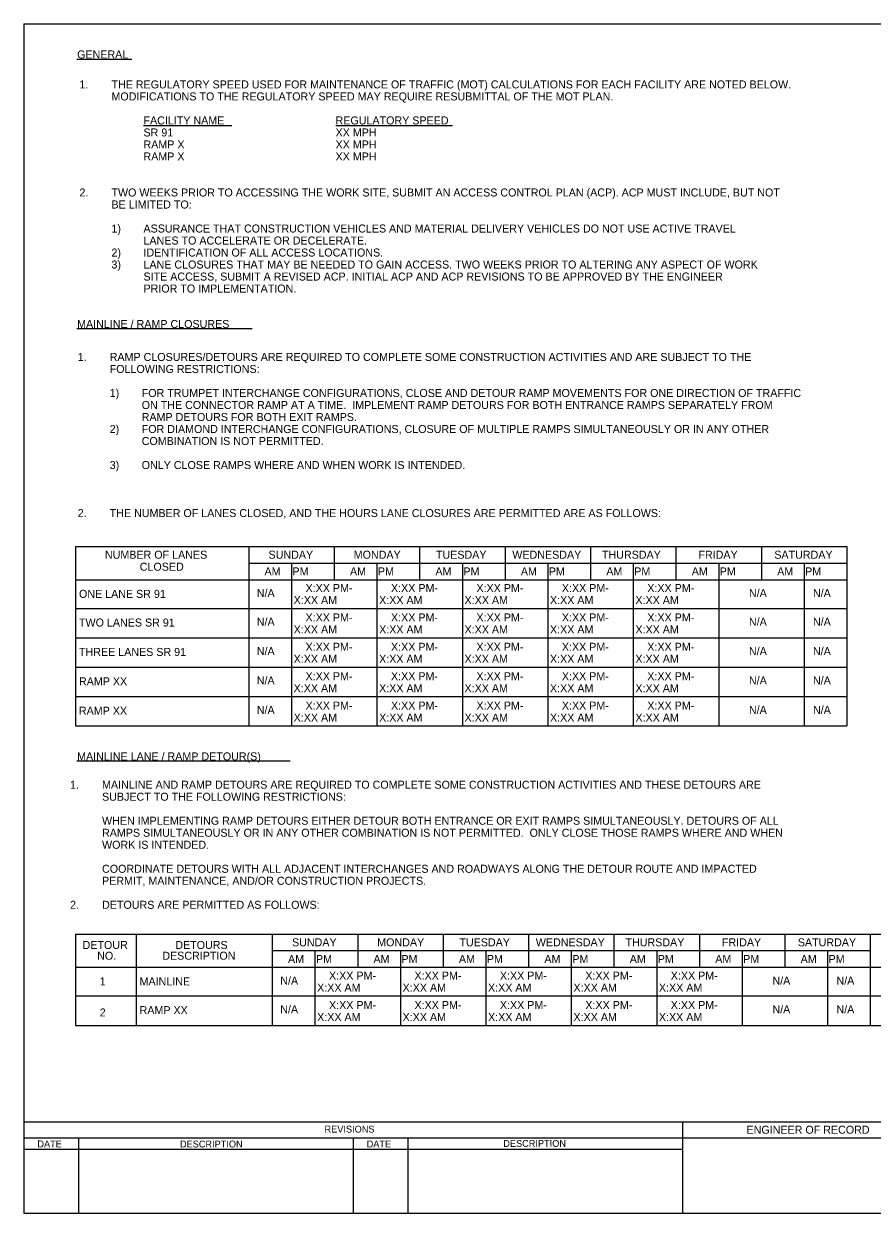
# Model space of a CAD drawing. Extents: x -0.71 to 1.34, y 0 to 0.87.
# Drawn here: x 0.046 to 0.664, y 0.004 to 0.871 of the extents above; entities that cross this region are included whole.
import ezdxf

# ---------------------------------------------------------------- set-up
doc = ezdxf.new("R2010")
doc.units = 0
for name, color, linetype in [('Default', 7, 'Continuous'), ('SheetBorder_dp', 7, 'Continuous'), ('SheetLines_dp', 7, 'Continuous'), ('TextLabel', 7, 'Continuous'), ('TextMisc', 7, 'Continuous')]:
    doc.layers.add(name, color=color, linetype=linetype)

msp = doc.modelspace()

# ---------------------------------------------------------------- linework, layer by layer
at = {"layer": 'Default'}
for p, q in [((0.08359, 0.49003), (0.6457, 0.49003)), ((0.08359, 0.49003), (0.08359, 0.35923)), ((0.2098, 0.49003), (0.2098, 0.35923)), ((0.27207, 0.49003), (0.27207, 0.46576)), ((0.33434, 0.49003), (0.33434, 0.46576)), ((0.39661, 0.49003), (0.39661, 0.46576)), ((0.45888, 0.49003), (0.45888, 0.46576)), ((0.52116, 0.49003), (0.52116, 0.46576)), ((0.58343, 0.49003), (0.58343, 0.46576)), ((0.6457, 0.49003), (0.6457, 0.35923)), ((0.2098, 0.4779), (0.6457, 0.4779)), ((0.24094, 0.4779), (0.24094, 0.35923)), ((0.30321, 0.4779), (0.30321, 0.35923)), ((0.36548, 0.4779), (0.36548, 0.35923)), ((0.42775, 0.4779), (0.42775, 0.35923)), ((0.49002, 0.4779), (0.49002, 0.35923)), ((0.55229, 0.4779), (0.55229, 0.35923)), ((0.61456, 0.4779), (0.61456, 0.35923)), ((0.08359, 0.46576), (0.6457, 0.46576)), ((0.08359, 0.44488), (0.6457, 0.44488)), ((0.08359, 0.42347), (0.6457, 0.42347)), ((0.08359, 0.40205), (0.6457, 0.40205)), ((0.08359, 0.38064), (0.6457, 0.38064)), ((0.08359, 0.35923), (0.6457, 0.35923)), ((0.08359, 0.20761), (0.74834, 0.20761)), ((0.08359, 0.20761), (0.08359, 0.14105)), ((0.12776, 0.20761), (0.12776, 0.14105)), ((0.22691, 0.20761), (0.22691, 0.14105)), ((0.28919, 0.20761), (0.28919, 0.18334)), ((0.35146, 0.20761), (0.35146, 0.18334)), ((0.41373, 0.20761), (0.41373, 0.18334)), ((0.476, 0.20761), (0.476, 0.18334)), ((0.53827, 0.20761), (0.53827, 0.18334)), ((0.60054, 0.20761), (0.60054, 0.18334)), ((0.66281, 0.20761), (0.66281, 0.14105)), ((0.22691, 0.19548), (0.66281, 0.19548)), ((0.25805, 0.19548), (0.25805, 0.14105)), ((0.32032, 0.19548), (0.32032, 0.14105)), ((0.38259, 0.19548), (0.38259, 0.14105)), ((0.44486, 0.19548), (0.44486, 0.14105)), ((0.50713, 0.19548), (0.50713, 0.14105)), ((0.56941, 0.19548), (0.56941, 0.14105)), ((0.63168, 0.19548), (0.63168, 0.14105)), ((0.08359, 0.18334), (0.74834, 0.18334)), ((0.08359, 0.16246), (0.74834, 0.16246)), ((0.08359, 0.14105), (0.74834, 0.14105))]:
    msp.add_line(p, q, dxfattribs=at)
at = {"layer": 'SheetBorder_dp'}
for p, q in [((0.04583, 0.87083), (0.04583, 0.00417)), ((0.04583, 0.87083), (1.32916, 0.87083)), ((0.04583, 0.07083), (1.32916, 0.07083)), ((0.04583, 0.00417), (1.32916, 0.00417))]:
    msp.add_line(p, q, dxfattribs=at)
at = {"layer": 'SheetLines_dp'}
for p, q in [((0.52583, 0.07083), (0.52583, 0.00417)), ((0.04583, 0.05917), (0.52583, 0.05917)), ((0.08583, 0.05917), (0.08583, 0.00417)), ((0.28583, 0.05917), (0.28583, 0.00417)), ((0.32583, 0.05917), (0.32583, 0.00417)), ((0.52621, 0.05917), (0.72084, 0.05917)), ((0.04583, 0.05083), (0.52583, 0.05083))]:
    msp.add_line(p, q, dxfattribs=at)
at = {"layer": 'TextLabel'}
for p, q in [((0.08444, 0.84513), (0.1246, 0.84513)), ((0.13314, 0.79678), (0.19739, 0.79678)), ((0.27326, 0.79678), (0.35823, 0.79678)), ((0.08444, 0.64875), (0.21227, 0.64875)), ((0.08444, 0.33368), (0.2401, 0.33368))]:
    msp.add_line(p, q, dxfattribs=at)

# ---------------------------------------------------------------- texts
at = {"layer": 'Default'}
for s, height, p in [('NUMBER OF LANES', 0.0058333, (0.10498, 0.48105)), ('SUNDAY', 0.005833, (0.22422, 0.48105)), ('MONDAY', 0.005833, (0.2863, 0.48105)), ('TUESDAY', 0.005833, (0.34622, 0.48105)), ('WEDNESDAY', 0.005833, (0.40188, 0.48105)), ('THURSDAY', 0.005833, (0.46724, 0.48105)), ('FRIDAY', 0.005833, (0.53753, 0.48105)), ('SATURDAY', 0.005833, (0.59284, 0.48105)), ('CLOSED', 0.005833, (0.13035, 0.4723)), ('AM    PM', 0.005833, (0.22131, 0.46891)), ('AM    PM', 0.005833, (0.28358, 0.46891)), ('AM    PM', 0.005833, (0.34585, 0.46891)), ('AM    PM', 0.005833, (0.40812, 0.46891)), ('AM    PM', 0.005833, (0.47039, 0.46891)), ('AM    PM', 0.005833, (0.53267, 0.46891)), ('AM    PM', 0.005833, (0.59494, 0.46891)), (' X:XX PM-', 0.005833, (0.24903, 0.45678)), (' X:XX PM-', 0.005833, (0.3113, 0.45678)), (' X:XX PM-', 0.005833, (0.37357, 0.45678)), (' X:XX PM-', 0.005833, (0.43584, 0.45678)), (' X:XX PM-', 0.005833, (0.49811, 0.45678)), ('ONE LANE SR 91', 0.0058333, (0.08607, 0.45252)), ('N/A', 0.005833, (0.21566, 0.45314)), ('      X:XX AM', 0.0058333, (0.22953, 0.44803)), ('      X:XX AM', 0.0058333, (0.2918, 0.44803)), ('      X:XX AM', 0.0058333, (0.35407, 0.44803)), ('      X:XX AM', 0.0058333, (0.41634, 0.44803)), ('      X:XX AM', 0.0058333, (0.47861, 0.44803)), ('N/A', 0.005833, (0.57437, 0.45314)), ('N/A', 0.005833, (0.62103, 0.45314)), ('TWO LANES SR 91', 0.0058333, (0.08607, 0.43164)), ('N/A', 0.005833, (0.21566, 0.43226)), (' X:XX PM-', 0.005833, (0.24903, 0.43537)), (' X:XX PM-', 0.005833, (0.3113, 0.43537)), (' X:XX PM-', 0.005833, (0.37357, 0.43537)), (' X:XX PM-', 0.005833, (0.43584, 0.43537)), (' X:XX PM-', 0.005833, (0.49811, 0.43537)), ('N/A', 0.005833, (0.57437, 0.43226)), ('N/A', 0.005833, (0.62103, 0.43226)), ('      X:XX AM', 0.0058333, (0.22953, 0.42662)), ('      X:XX AM', 0.0058333, (0.2918, 0.42662)), ('      X:XX AM', 0.0058333, (0.35407, 0.42662)), ('      X:XX AM', 0.0058333, (0.41634, 0.42662)), ('      X:XX AM', 0.0058333, (0.47861, 0.42662)), ('THREE LANES SR 91', 0.0058333, (0.08607, 0.41022)), ('N/A', 0.005833, (0.21566, 0.41085)), (' X:XX PM-', 0.005833, (0.24903, 0.41395)), (' X:XX PM-', 0.005833, (0.3113, 0.41395)), (' X:XX PM-', 0.005833, (0.37357, 0.41395)), (' X:XX PM-', 0.005833, (0.43584, 0.41395)), (' X:XX PM-', 0.005833, (0.49811, 0.41395)), ('N/A', 0.005833, (0.57437, 0.41085)), ('N/A', 0.005833, (0.62103, 0.41085)), ('      X:XX AM', 0.0058333, (0.22953, 0.4052)), ('      X:XX AM', 0.0058333, (0.2918, 0.4052)), ('      X:XX AM', 0.0058333, (0.35407, 0.4052)), ('      X:XX AM', 0.0058333, (0.41634, 0.4052)), ('      X:XX AM', 0.0058333, (0.47861, 0.4052)), ('RAMP XX', 0.005833, (0.08607, 0.38881)), ('N/A', 0.005833, (0.21566, 0.38943)), (' X:XX PM-', 0.005833, (0.24903, 0.39254)), (' X:XX PM-', 0.005833, (0.3113, 0.39254)), (' X:XX PM-', 0.005833, (0.37357, 0.39254)), (' X:XX PM-', 0.005833, (0.43584, 0.39254)), (' X:XX PM-', 0.005833, (0.49811, 0.39254)), ('N/A', 0.005833, (0.57437, 0.38943)), ('N/A', 0.005833, (0.62103, 0.38943)), ('      X:XX AM', 0.0058333, (0.22953, 0.38379)), ('      X:XX AM', 0.0058333, (0.2918, 0.38379)), ('      X:XX AM', 0.0058333, (0.35407, 0.38379)), ('      X:XX AM', 0.0058333, (0.41634, 0.38379)), ('      X:XX AM', 0.0058333, (0.47861, 0.38379)), ('RAMP XX', 0.005833, (0.08601, 0.3674)), ('N/A', 0.005833, (0.21566, 0.36802)), (' X:XX PM-', 0.005833, (0.24903, 0.37113)), (' X:XX PM-', 0.005833, (0.3113, 0.37113)), (' X:XX PM-', 0.005833, (0.37357, 0.37113)), (' X:XX PM-', 0.005833, (0.43584, 0.37113)), (' X:XX PM-', 0.005833, (0.49811, 0.37113)), ('N/A', 0.005833, (0.57437, 0.36802)), ('N/A', 0.005833, (0.62103, 0.36802)), ('      X:XX AM', 0.0058333, (0.22953, 0.36238)), ('      X:XX AM', 0.0058333, (0.2918, 0.36238)), ('      X:XX AM', 0.0058333, (0.35407, 0.36238)), ('      X:XX AM', 0.0058333, (0.41634, 0.36238)), ('      X:XX AM', 0.0058333, (0.47861, 0.36238)), ('DETOUR', 0.005833, (0.08869, 0.19669)), ('DETOURS', 0.005833, (0.15626, 0.19669)), ('SUNDAY', 0.005833, (0.24133, 0.19863)), ('MONDAY', 0.005833, (0.30342, 0.19863)), ('TUESDAY', 0.005833, (0.36333, 0.19863)), ('WEDNESDAY', 0.005833, (0.419, 0.19863)), ('THURSDAY', 0.005833, (0.48436, 0.19863)), ('FRIDAY', 0.005833, (0.55465, 0.19863)), ('SATURDAY', 0.005833, (0.60996, 0.19863)), ('NO.', 0.005833, (0.09931, 0.18887)), ('DESCRIPTION', 0.0058333, (0.1468, 0.18887)), ('AM    PM', 0.005833, (0.23842, 0.18649)), ('AM    PM', 0.005833, (0.3007, 0.18649)), ('AM    PM', 0.005833, (0.36297, 0.18649)), ('AM    PM', 0.005833, (0.42524, 0.18649)), ('AM    PM', 0.005833, (0.48751, 0.18649)), ('AM    PM', 0.005833, (0.54978, 0.18649)), ('AM    PM', 0.005833, (0.61205, 0.18649)), ('1', 0.00583, (0.10116, 0.1701)), ('MAINLINE', 0.005833, (0.13024, 0.1701)), ('N/A', 0.005833, (0.23277, 0.17072)), (' X:XX PM-', 0.005833, (0.26614, 0.17436)), (' X:XX PM-', 0.005833, (0.32841, 0.17436)), (' X:XX PM-', 0.005833, (0.39068, 0.17436)), (' X:XX PM-', 0.005833, (0.45295, 0.17436)), (' X:XX PM-', 0.005833, (0.51522, 0.17436)), ('N/A', 0.005833, (0.59149, 0.17072)), ('N/A', 0.005833, (0.63815, 0.17072)), ('      X:XX AM', 0.0058333, (0.24664, 0.16561)), ('      X:XX AM', 0.0058333, (0.30891, 0.16561)), ('      X:XX AM', 0.0058333, (0.37118, 0.16561)), ('      X:XX AM', 0.0058333, (0.43345, 0.16561)), ('      X:XX AM', 0.0058333, (0.49573, 0.16561)), (' X:XX PM-', 0.005833, (0.26614, 0.15295)), (' X:XX PM-', 0.005833, (0.32841, 0.15295)), (' X:XX PM-', 0.005833, (0.39068, 0.15295)), (' X:XX PM-', 0.005833, (0.45295, 0.15295)), (' X:XX PM-', 0.005833, (0.51522, 0.15295)), ('2', 0.00583, (0.10116, 0.1475)), ('RAMP XX', 0.005833, (0.13024, 0.14921)), ('N/A', 0.005833, (0.23277, 0.14984)), ('      X:XX AM', 0.0058333, (0.24664, 0.1442)), ('      X:XX AM', 0.0058333, (0.30891, 0.1442)), ('      X:XX AM', 0.0058333, (0.37118, 0.1442)), ('      X:XX AM', 0.0058333, (0.43345, 0.1442)), ('      X:XX AM', 0.0058333, (0.49573, 0.1442)), ('N/A', 0.005833, (0.59149, 0.14984)), ('N/A', 0.005833, (0.63815, 0.14984))]:
    msp.add_text(s, height=height, dxfattribs=at).set_placement(p)
at = {"layer": 'TextLabel'}
for s, height, p in [('GENERAL', 0.005833, (0.08471, 0.84555)), ('1. ', 0.005833, (0.0864, 0.82374)), ('THE REGULATORY SPEED USED FOR MAINTENANCE OF TRAFFIC (MOT) CALCULATIONS FOR EACH FACILITY ARE NOTED BELOW. ', 0.00583333, (0.10973, 0.82374)), ('MODIFICATIONS TO THE REGULATORY SPEED MAY REQUIRE RESUBMITTAL OF THE MOT PLAN.', 0.0058333, (0.10973, 0.81499)), ('FACILITY NAME', 0.0058333, (0.13307, 0.79749)), ('REGULATORY SPEED', 0.0058333, (0.27307, 0.79749)), ('SR 91', 0.005833, (0.13307, 0.78874)), ('XX MPH', 0.005833, (0.27307, 0.78874)), ('RAMP X', 0.005833, (0.13307, 0.77999)), ('XX MPH', 0.005833, (0.27307, 0.77999)), ('RAMP X', 0.005833, (0.13307, 0.77124)), ('XX MPH', 0.005833, (0.27307, 0.77124)), ('2.', 0.005833, (0.0864, 0.74499)), ('TWO WEEKS PRIOR TO ACCESSING THE WORK SITE, SUBMIT AN ACCESS CONTROL PLAN (ACP). ACP MUST INCLUDE, BUT NOT ', 0.00583333, (0.10973, 0.74499)), ('BE LIMITED TO:', 0.0058333, (0.10973, 0.73624)), ('1)', 0.005833, (0.10973, 0.71874)), ('ASSURANCE THAT CONSTRUCTION VEHICLES AND MATERIAL DELIVERY VEHICLES DO NOT USE ACTIVE TRAVEL ', 0.0058333, (0.13307, 0.71874)), ('LANES TO ACCELERATE OR DECELERATE.', 0.0058333, (0.13307, 0.70999)), ('2)', 0.005833, (0.10973, 0.70124)), ('IDENTIFICATION OF ALL ACCESS LOCATIONS.', 0.0058333, (0.13307, 0.70124)), ('3)', 0.005833, (0.10973, 0.69249)), ('LANE CLOSURES THAT MAY BE NEEDED TO GAIN ACCESS. TWO WEEKS PRIOR TO ALTERING ANY ASPECT OF WORK ', 0.0058333, (0.13307, 0.69249)), ('SITE ACCESS, SUBMIT A REVISED ACP. INITIAL ACP AND ACP REVISIONS TO BE APPROVED BY THE ENGINEER ', 0.0058333, (0.13307, 0.68374)), ('PRIOR TO IMPLEMENTATION.', 0.0058333, (0.13307, 0.67499)), ('MAINLINE / RAMP CLOSURES', 0.0058333, (0.08471, 0.64918)), ('1.', 0.005833, (0.08512, 0.62515)), ('RAMP CLOSURES/DETOURS ARE REQUIRED TO COMPLETE SOME CONSTRUCTION ACTIVITIES AND ARE SUBJECT TO THE ', 0.0058333, (0.10845, 0.62515)), ('FOLLOWING RESTRICTIONS:', 0.0058333, (0.10845, 0.6164)), ('1)', 0.005833, (0.10845, 0.5989)), ('FOR TRUMPET INTERCHANGE CONFIGURATIONS, CLOSE AND DETOUR RAMP MOVEMENTS FOR ONE DIRECTION OF TRAFFIC ', 0.00583333, (0.13178, 0.5989)), ('ON THE CONNECTOR RAMP AT A TIME.  IMPLEMENT RAMP DETOURS FOR BOTH ENTRANCE RAMPS SEPARATELY FROM ', 0.0058333, (0.13178, 0.59015)), ('RAMP DETOURS FOR BOTH EXIT RAMPS.', 0.0058333, (0.13178, 0.5814)), ('2)', 0.005833, (0.10845, 0.57265)), ('FOR DIAMOND INTERCHANGE CONFIGURATIONS, CLOSURE OF MULTIPLE RAMPS SIMULTANEOUSLY OR IN ANY OTHER ', 0.0058333, (0.13178, 0.57265)), ('COMBINATION IS NOT PERMITTED.', 0.0058333, (0.13178, 0.5639)), ('3)', 0.005833, (0.10845, 0.5464)), ('ONLY CLOSE RAMPS WHERE AND WHEN WORK IS INTENDED.', 0.0058333, (0.13178, 0.5464)), ('2.', 0.005833, (0.08512, 0.5114)), ('THE NUMBER OF LANES CLOSED, AND THE HOURS LANE CLOSURES ARE PERMITTED ARE AS FOLLOWS:', 0.0058333, (0.10845, 0.5114)), ('MAINLINE LANE / RAMP DETOUR(S)', 0.0058333, (0.08471, 0.33411)), ('1.', 0.005833, (0.07954, 0.31347)), ('MAINLINE AND RAMP DETOURS ARE REQUIRED TO COMPLETE SOME CONSTRUCTION ACTIVITIES AND THESE DETOURS ARE ', 0.00583333, (0.10287, 0.31347)), ('SUBJECT TO THE FOLLOWING RESTRICTIONS:', 0.0058333, (0.10287, 0.30472)), ('WHEN IMPLEMENTING RAMP DETOURS EITHER DETOUR BOTH ENTRANCE OR EXIT RAMPS SIMULTANEOUSLY. DETOURS OF ALL ', 0.00583333, (0.10287, 0.28722)), ('RAMPS SIMULTANEOUSLY OR IN ANY OTHER COMBINATION IS NOT PERMITTED.  ONLY CLOSE THOSE RAMPS WHERE AND WHEN ', 0.00583333, (0.10287, 0.27847)), ('WORK IS INTENDED.', 0.0058333, (0.10287, 0.26972)), ('COORDINATE DETOURS WITH ALL ADJACENT INTERCHANGES AND ROADWAYS ALONG THE DETOUR ROUTE AND IMPACTED ', 0.0058333, (0.10287, 0.25222)), ('PERMIT, MAINTENANCE, AND/OR CONSTRUCTION PROJECTS.\xa0 ', 0.0058333, (0.10287, 0.24347)), ('2.', 0.005833, (0.07954, 0.22597)), ('DETOURS ARE PERMITTED AS FOLLOWS:', 0.0058333, (0.10287, 0.22597))]:
    msp.add_text(s, height=height, dxfattribs=at).set_placement(p)
at = {"layer": 'TextMisc'}
for s, height, p in [('REVISIONS', 0.005, (0.26504, 0.06293)), ('ENGINEER OF RECORD', 0.0058333, (0.57258, 0.06208))]:
    msp.add_text(s, height=height, dxfattribs=at).set_placement(p)
for s, rotation, p in [('DATE', 359.86925, (0.05574, 0.05216)), ('DESCRIPTION', 0.04975, (0.15966, 0.05206)), ('DATE', 359.86925, (0.29574, 0.05211)), ('DESCRIPTION', 0.04975, (0.3953, 0.05248))]:
    msp.add_text(s, height=0.005, rotation=rotation, dxfattribs=at).set_placement(p)

doc.saveas('drawing.dxf')
